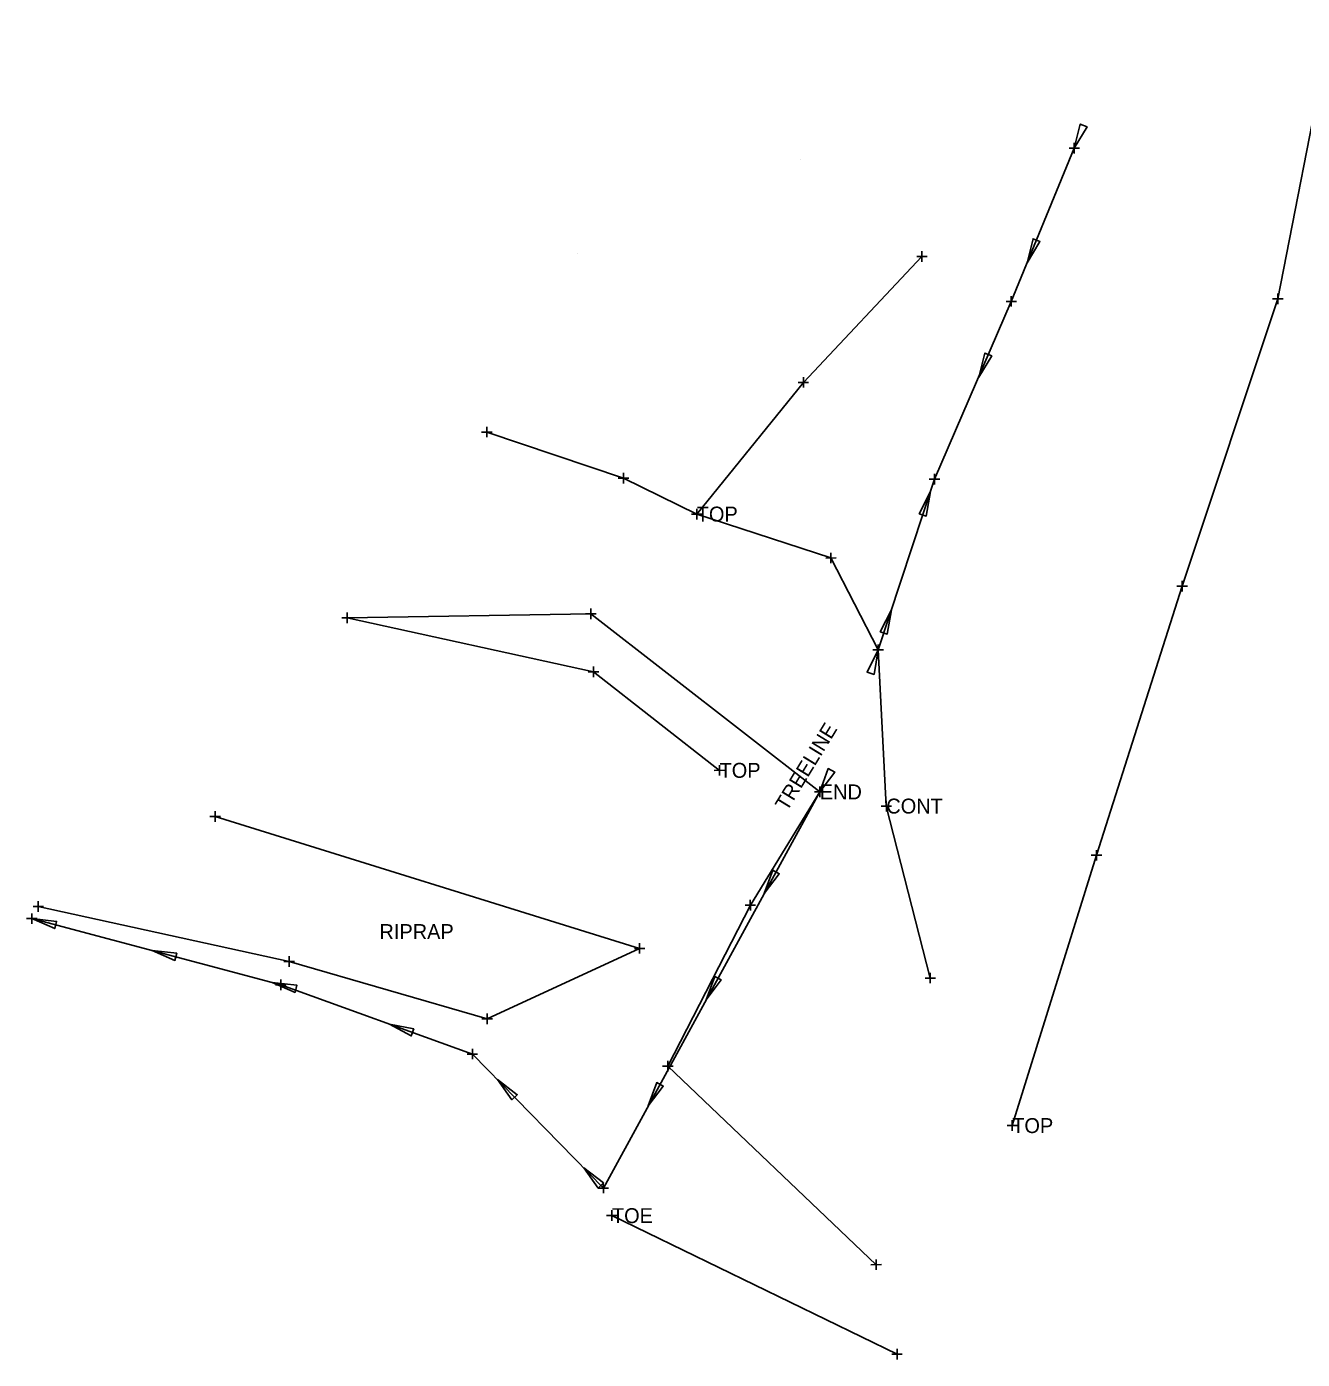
# Model space of a CAD drawing. Extents: x 1733239 to 1734352, y 466612 to 468622.
# Drawn here: x 1733734.5 to 1733888.4, y 467831.5 to 467992.2 of the extents above; entities that cross this region are included whole.
import ezdxf

# ---------------------------------------------------------------- set-up
doc = ezdxf.new("R2010")
doc.units = 0
for name, color, linetype in [('S_Terrain_Boundary', 7, 'Continuous'), ('S_Terrain_Breaklines', 7, 'Continuous'), ('S_Terrain_Holes', 7, 'Continuous'), ('S_Terrain_Major_Contours', 7, 'Continuous'), ('S_Terrain_Minor_Contours', 7, 'Continuous'), ('S_Terrain_Triangles', 7, 'Continuous'), ('S_Terrain_Voids', 7, 'Continuous'), ('S_Traffic_Sign_SinglePost', 7, 'Continuous')]:
    doc.layers.add(name, color=color, linetype=linetype)

msp = doc.modelspace()

# ---------------------------------------------------------------- linework, layer by layer
at = {"layer": 'S_Terrain_Boundary'}
for points in [[(1733789.99, 467943.32), (1733806.46, 467937.75), (1733815.3, 467933.43), (1733831.49, 467928.14), (1733837.19, 467917.05)], [(1733838.17, 467898.21), (1733837.19, 467917.05)], [(1733838.17, 467898.21), (1733843.47, 467877.47)]]:
    msp.add_lwpolyline(points, dxfattribs=at)
at = {"layer": 'S_Terrain_Breaklines'}
msp.add_lwpolyline([(1733836.95, 467842.89), (1733811.8, 467866.84), (1733821.77, 467886.25), (1733830.14, 467899.92), (1733802.51, 467921.4), (1733773.14, 467920.9)], dxfattribs=at)
at = {"layer": 'S_Terrain_Holes'}
for points in [[(1733853.36, 467859.67), (1733863.53, 467892.27), (1733873.85, 467924.74), (1733885.4, 467959.39), (1733891.32, 467989.61), (1733902.91, 468023.32), (1733917.22, 468057.86), (1733927.15, 468090.49), (1733931.35, 468108.36)], [(1733815.3, 467933.43), (1733828.16, 467949.31), (1733842.47, 467964.5)], [(1733818.05, 467902.52), (1733802.84, 467914.4), (1733773.14, 467920.9)], [(1733805.07, 467848.81), (1733839.47, 467832.11)]]:
    msp.add_lwpolyline(points, dxfattribs=at)
at = {"layer": 'S_Terrain_Major_Contours'}
for p, q in [((1733827.85, 467976.23), (1733827.85, 467976.23)), ((1733800.89, 467964.89), (1733800.89, 467964.89))]:
    msp.add_line(p, q, dxfattribs=at)
at = {"layer": 'S_Terrain_Minor_Contours'}
for p, q in [((1733860.84, 467976.92), (1733860.84, 467978.19)), ((1733860.21, 467977.55), (1733861.48, 467977.55)), ((1733860.84, 467977.55), (1733860.84, 467977.55)), ((1733842.47, 467963.86), (1733842.47, 467965.13)), ((1733841.83, 467964.5), (1733843.11, 467964.5)), ((1733842.47, 467964.5), (1733842.47, 467964.5)), ((1733852.62, 467959.09), (1733853.89, 467959.09)), ((1733853.25, 467958.45), (1733853.25, 467959.73)), ((1733853.25, 467959.09), (1733853.25, 467959.09)), ((1733884.76, 467959.39), (1733886.04, 467959.4)), ((1733885.4, 467958.76), (1733885.4, 467960.03)), ((1733885.4, 467959.39), (1733885.4, 467959.39)), ((1733827.52, 467949.31), (1733828.79, 467949.31)), ((1733828.16, 467948.68), (1733828.16, 467949.95)), ((1733828.16, 467949.31), (1733828.16, 467949.31)), ((1733789.35, 467943.32), (1733790.62, 467943.32)), ((1733789.99, 467942.69), (1733789.98, 467943.96)), ((1733789.99, 467943.32), (1733789.99, 467943.32)), ((1733805.82, 467937.75), (1733807.1, 467937.75)), ((1733806.46, 467937.12), (1733806.46, 467938.39)), ((1733806.46, 467937.75), (1733806.46, 467937.75)), ((1733843.35, 467937.64), (1733844.63, 467937.64)), ((1733843.99, 467937), (1733843.99, 467938.28)), ((1733843.99, 467937.64), (1733843.99, 467937.64)), ((1733814.66, 467933.43), (1733815.94, 467933.43)), ((1733814.66, 467933.43), (1733815.94, 467933.43)), ((1733815.3, 467932.79), (1733815.3, 467934.06)), ((1733815.3, 467932.79), (1733815.3, 467934.06)), ((1733815.3, 467933.43), (1733815.3, 467933.43)), ((1733815.3, 467933.43), (1733815.3, 467933.43)), ((1733830.86, 467928.13), (1733832.13, 467928.14)), ((1733831.49, 467927.5), (1733831.49, 467928.77)), ((1733831.49, 467928.14), (1733831.49, 467928.14)), ((1733873.22, 467924.74), (1733874.49, 467924.74)), ((1733873.85, 467924.1), (1733873.85, 467925.38)), ((1733873.85, 467924.74), (1733873.85, 467924.74)), ((1733773.14, 467920.26), (1733773.14, 467921.54)), ((1733773.14, 467920.26), (1733773.14, 467921.54)), ((1733802.51, 467920.77), (1733802.51, 467922.04)), ((1733772.5, 467920.9), (1733773.77, 467920.9)), ((1733772.5, 467920.9), (1733773.77, 467920.9)), ((1733773.14, 467920.9), (1733773.14, 467920.9)), ((1733773.14, 467920.9), (1733773.14, 467920.9)), ((1733801.88, 467921.4), (1733803.15, 467921.4)), ((1733802.51, 467921.4), (1733802.51, 467921.4)), ((1733836.56, 467917.05), (1733837.83, 467917.05)), ((1733836.56, 467917.05), (1733837.83, 467917.05)), ((1733837.2, 467916.41), (1733837.19, 467917.68)), ((1733837.2, 467916.41), (1733837.19, 467917.68)), ((1733837.19, 467917.05), (1733837.19, 467917.05)), ((1733837.19, 467917.05), (1733837.19, 467917.05)), ((1733802.21, 467914.4), (1733803.48, 467914.4)), ((1733802.84, 467913.76), (1733802.84, 467915.03)), ((1733802.84, 467914.4), (1733802.84, 467914.4)), ((1733817.41, 467902.52), (1733818.69, 467902.53)), ((1733818.05, 467901.89), (1733818.05, 467903.16)), ((1733818.05, 467902.52), (1733818.05, 467902.52)), ((1733829.5, 467899.92), (1733830.77, 467899.92)), ((1733829.5, 467899.92), (1733830.77, 467899.92)), ((1733830.14, 467899.29), (1733830.14, 467900.56)), ((1733830.14, 467899.29), (1733830.14, 467900.56)), ((1733830.14, 467899.92), (1733830.14, 467899.92)), ((1733830.14, 467899.92), (1733830.14, 467899.92)), ((1733757.19, 467896.32), (1733757.19, 467897.59)), ((1733837.54, 467898.21), (1733838.81, 467898.21)), ((1733838.18, 467897.57), (1733838.17, 467898.85)), ((1733838.17, 467898.21), (1733838.17, 467898.21)), ((1733756.56, 467896.96), (1733757.83, 467896.96)), ((1733757.19, 467896.96), (1733757.19, 467896.96)), ((1733863.53, 467891.64), (1733863.53, 467892.91)), ((1733862.9, 467892.27), (1733864.17, 467892.27)), ((1733863.53, 467892.27), (1733863.53, 467892.27)), ((1733735.87, 467885.46), (1733735.87, 467886.73)), ((1733821.13, 467886.25), (1733822.4, 467886.25)), ((1733821.77, 467885.61), (1733821.76, 467886.89)), ((1733821.77, 467886.25), (1733821.77, 467886.25)), ((1733734.46, 467884.63), (1733735.73, 467884.63)), ((1733735.1, 467884), (1733735.1, 467885.27)), ((1733735.1, 467884.63), (1733735.1, 467884.63)), ((1733735.23, 467886.09), (1733736.51, 467886.1)), ((1733735.87, 467886.1), (1733735.87, 467886.1)), ((1733808.41, 467880.41), (1733808.41, 467881.69)), ((1733766.13, 467878.82), (1733766.12, 467880.09)), ((1733807.78, 467881.05), (1733809.05, 467881.05)), ((1733808.41, 467881.05), (1733808.41, 467881.05)), ((1733765.49, 467879.45), (1733766.76, 467879.46)), ((1733766.13, 467879.46), (1733766.13, 467879.46)), ((1733843.47, 467876.83), (1733843.47, 467878.1)), ((1733764.5, 467876.65), (1733765.77, 467876.65)), ((1733765.13, 467876.01), (1733765.13, 467877.29)), ((1733765.13, 467876.65), (1733765.13, 467876.65)), ((1733842.84, 467877.46), (1733844.11, 467877.47)), ((1733843.47, 467877.47), (1733843.47, 467877.47)), ((1733789.37, 467872.56), (1733790.64, 467872.56)), ((1733790.01, 467871.92), (1733790, 467873.19)), ((1733790.01, 467872.56), (1733790.01, 467872.56)), ((1733788.23, 467867.67), (1733788.23, 467868.94)), ((1733787.59, 467868.3), (1733788.87, 467868.3)), ((1733788.23, 467868.3), (1733788.23, 467868.3)), ((1733811.8, 467866.21), (1733811.8, 467867.48)), ((1733811.16, 467866.84), (1733812.44, 467866.84)), ((1733811.8, 467866.84), (1733811.8, 467866.84)), ((1733852.73, 467859.67), (1733854, 467859.67)), ((1733853.36, 467859.04), (1733853.36, 467860.31)), ((1733853.36, 467859.67), (1733853.36, 467859.67)), ((1733804.04, 467851.51), (1733804.03, 467852.78)), ((1733803.4, 467852.14), (1733804.67, 467852.14)), ((1733804.04, 467852.14), (1733804.04, 467852.14)), ((1733805.07, 467848.18), (1733805.07, 467849.45)), ((1733804.43, 467848.81), (1733805.71, 467848.81)), ((1733805.07, 467848.81), (1733805.07, 467848.81)), ((1733836.31, 467842.89), (1733837.58, 467842.9)), ((1733836.95, 467842.26), (1733836.95, 467843.53)), ((1733836.95, 467842.89), (1733836.95, 467842.89)), ((1733838.83, 467832.11), (1733840.1, 467832.11)), ((1733839.47, 467831.47), (1733839.47, 467832.75)), ((1733839.47, 467832.11), (1733839.47, 467832.11))]:
    msp.add_line(p, q, dxfattribs=at)
at = {"layer": 'S_Terrain_Triangles'}
msp.add_lwpolyline([(1733735.87, 467886.1), (1733766.13, 467879.46), (1733790.01, 467872.56), (1733808.41, 467881.05), (1733757.19, 467896.96)], dxfattribs=at)
at = {"layer": 'S_Terrain_Voids'}
for p, q in [((1733860.84, 467977.55), (1733860.84, 467977.55)), ((1733855.16, 467963.73), (1733855.16, 467963.73)), ((1733849.31, 467949.95), (1733849.31, 467949.95)), ((1733843.5, 467936.15), (1733843.5, 467936.15)), ((1733838.8, 467921.9), (1733838.8, 467921.9)), ((1733837.19, 467917.05), (1733837.19, 467917.05)), ((1733830.14, 467899.92), (1733830.14, 467899.92)), ((1733823.44, 467887.66), (1733823.44, 467887.66)), ((1733735.1, 467884.63), (1733735.1, 467884.63)), ((1733749.59, 467880.78), (1733749.59, 467880.78)), ((1733764.09, 467876.93), (1733764.09, 467876.93)), ((1733816.44, 467874.85), (1733816.44, 467874.85)), ((1733778.22, 467871.92), (1733778.22, 467871.92)), ((1733791.26, 467865.21), (1733791.26, 467865.21)), ((1733809.44, 467862.04), (1733809.44, 467862.04)), ((1733801.67, 467854.56), (1733801.67, 467854.56))]:
    msp.add_line(p, q, dxfattribs=at)
for points in [[(1733860.84, 467977.55), (1733861.56, 467980.47), (1733862.38, 467980.13)], [(1733855.16, 467963.73), (1733855.88, 467966.64), (1733856.7, 467966.3)], [(1733849.31, 467949.95), (1733850.07, 467952.85), (1733850.89, 467952.5)], [(1733843.5, 467936.15), (1733842.99, 467933.19), (1733842.14, 467933.47)], [(1733838.8, 467921.9), (1733838.29, 467918.95), (1733837.44, 467919.23)], [(1733837.19, 467917.05), (1733836.69, 467914.09), (1733835.84, 467914.37)], [(1733830.14, 467899.92), (1733831.17, 467902.74), (1733831.95, 467902.31)], [(1733823.44, 467887.66), (1733824.47, 467890.47), (1733825.25, 467890.05)], [(1733735.1, 467884.63), (1733738.08, 467884.3), (1733737.85, 467883.44)], [(1733749.59, 467880.78), (1733752.57, 467880.45), (1733752.35, 467879.59)], [(1733764.09, 467876.93), (1733767.07, 467876.59), (1733766.84, 467875.73)], [(1733816.44, 467874.85), (1733817.47, 467877.67), (1733818.25, 467877.24)], [(1733778.22, 467871.92), (1733781.16, 467871.33), (1733780.86, 467870.49)], [(1733791.26, 467865.21), (1733793.65, 467863.4), (1733793.01, 467862.78)], [(1733809.44, 467862.04), (1733810.47, 467864.86), (1733811.25, 467864.43)], [(1733801.67, 467854.56), (1733804.06, 467852.75), (1733803.42, 467852.13)]]:
    msp.add_lwpolyline(points, close=True, dxfattribs=at)
for points in [[(1733860.84, 467977.55), (1733853.25, 467959.09), (1733843.99, 467937.64), (1733837.19, 467917.05)], [(1733735.1, 467884.63), (1733765.13, 467876.65), (1733788.23, 467868.3), (1733804.04, 467852.14), (1733830.14, 467899.92)]]:
    msp.add_lwpolyline(points, dxfattribs=at)

# ---------------------------------------------------------------- texts
at = {"layer": 'S_Traffic_Sign_SinglePost'}
for s, p in [('TOP', (1733815.3, 467932.53)), ('TOP', (1733815.3, 467932.53)), ('TOP', (1733818.05, 467901.62)), ('END', (1733830.14, 467899.02)), ('END', (1733830.14, 467899.02)), ('CONT', (1733838.17, 467897.31)), ('RIPRAP', (1733777.02, 467882.17)), ('TOP', (1733853.36, 467858.77)), ('TOE', (1733805.07, 467847.91))]:
    msp.add_text(s, height=1.8, dxfattribs=at).set_placement(p)
msp.add_text('TREELINE', height=1.8, rotation=58.5274, dxfattribs=at).set_placement((1733826.18, 467897.48))

doc.saveas('drawing.dxf')
